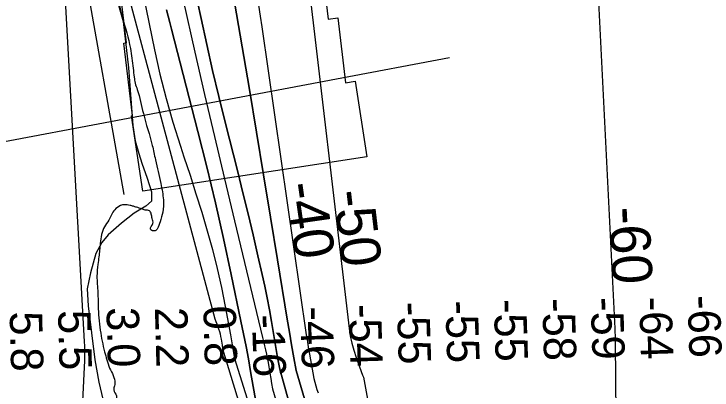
# Model space of a CAD drawing. Extents: x 3694830 to 3732949, y 415201 to 440970.
# Drawn here: x 3716134 to 3717574, y 423394 to 424171 of the extents above; entities that cross this region are included whole.
import ezdxf

# ---------------------------------------------------------------- set-up
doc = ezdxf.new("R2010")
doc.units = 0
for name, color, linetype in [('V-RIVR-EDGE', 7, 'Continuous'), ('V-RIVR-RANG', 7, 'Continuous'), ('V-RRAP-FSHR', 7, 'Continuous'), ('V-RRAP-RVMT', 7, 'Continuous'), ('V-SITE-VEGE', 7, 'Continuous'), ('V-TOPO-DPTH', 7, 'Continuous'), ('V-TOPO-MAJR', 7, 'Continuous'), ('V-TOPO-MAJR-IDEN', 7, 'Continuous'), ('V-TOPO-MINR', 7, 'Continuous'), ('V-TOPO-MINR-IDEN', 7, 'Continuous'), ('V-TOPO-WATR', 7, 'Continuous')]:
    doc.layers.add(name, color=color, linetype=linetype)

msp = doc.modelspace()

# ---------------------------------------------------------------- linework, layer by layer
at = {"layer": 'V-RIVR-EDGE'}
for points in [[(3716285.2, 433216.7), (3716310.4, 433178.2), (3716330.2, 433149.7), (3716351.4, 433122.5), (3716380.7, 433076.8), (3716399.1, 433050.5), (3716447.8, 432976.2), (3716475.3, 432930.5), (3716501.8, 432891.1), (3716527.5, 432851.2), (3716586, 432749.3), (3716608.1, 432711.8), (3716608.1, 432707.7), (3716608.1, 432700.4), (3716613, 432690.9), (3716627.4, 432664.2), (3716633.3, 432651.6), (3716643.2, 432639.3), (3716675.2, 432589.5), (3716706.2, 432538.3), (3716726.9, 432498), (3716741.3, 432463.6), (3716748.5, 432442.8), (3716788.6, 432378.5), (3716817.4, 432339.6), (3716842.2, 432297.4), (3716889.5, 432209.6), (3716920.5, 432144.4), (3716938, 432109.6), (3716956.5, 432075.2), (3716988.9, 432022.6), (3717009.2, 431986.9), (3717026.3, 431960.1), (3717062.3, 431897.6), (3717093.4, 431840.1), (3717112.3, 431799.9), (3717149.1, 431711.1), (3717176.5, 431644.6), (3717201.2, 431580.8), (3717210.7, 431556.4), (3717248.5, 431478.9), (3717267.8, 431435.5), (3717289.4, 431392.9), (3717306.5, 431346.8), (3717328.1, 431301), (3717339.3, 431276.6), (3717352.3, 431244), (3717362.7, 431226.4), (3717376.2, 431205.5), (3717389.3, 431178.4), (3717401.4, 431141.7), (3717407.2, 431113.2), (3717409.9, 431101.9), (3717419.7, 431075.6), (3717452.5, 430968.9), (3717469.1, 430916.8), (3717483.4, 430865.2), (3717505.5, 430810), (3717526.6, 430753.4), (3717540.5, 430715.4), (3717579.1, 430593.2), (3717599.3, 430526.3), (3717616.3, 430474.7), (3717628.9, 430437.1), (3717638.7, 430405), (3717647.7, 430364.3), (3717653.5, 430331.7), (3717658.4, 430314.5), (3717667.9, 430290.1), (3717679.5, 430260.7), (3717690.3, 430242.1), (3717695.7, 430221.3), (3717698.4, 430200), (3717697.9, 430172), (3717701.4, 430153), (3717705.9, 430140.8), (3717716.3, 430119.9), (3717728, 430100.5), (3717735.6, 430076.5), (3717737.8, 430059.3), (3717749, 430029.9), (3717760.8, 430011.8), (3717771.6, 429990), (3717776.5, 429968.3), (3717783.2, 429941.6), (3717791.7, 429917.6), (3717803.4, 429898.6), (3717812.4, 429876.5), (3717819.2, 429857.4), (3717834.9, 429816.7), (3717846.5, 429770.1), (3717854.1, 429734.8), (3717863.5, 429706.3), (3717878.8, 429667.4), (3717891.4, 429622.6), (3717903.5, 429586.4), (3717917.8, 429530.3), (3717931.7, 429476.4), (3717959.5, 429363.8), (3717976.5, 429307.2), (3717987.2, 429262.4), (3718014.1, 429153.9), (3718027.5, 429090.1), (3718040.5, 429028.1), (3718052.5, 428962.5), (3718057.8, 428920), (3718056.9, 428903.3), (3718056.9, 428887.9), (3718057.7, 428868.4), (3718061.3, 428850.8), (3718065.8, 428833.6), (3718082.4, 428779.3), (3718091.3, 428748.1), (3718100.3, 428711), (3718111.4, 428657.1), (3718116.4, 428631.8), (3718128.3, 428526), (3718136.8, 428473.1), (3718141.7, 428440), (3718152.3, 428360.9), (3718163.9, 428291.2), (3718171, 428256.4), (3718178.2, 428236.5), (3718193.9, 428178.6), (3718199.7, 428157.3), (3718197.9, 428150.1), (3718196.5, 428133.3), (3718197.4, 428121.1), (3718204.1, 428098), (3718215.4, 428075.4), (3718228, 428049.6), (3718240.1, 428011.6), (3718242.7, 427978.6), (3718251.1, 427901.2), (3718254.2, 427852.9), (3718257.7, 427822.1), (3718271.5, 427736.2), (3718281.7, 427671.9), (3718287.9, 427606.3), (3718295.9, 427551.6), (3718303.9, 427477.4), (3718310.1, 427447.1), (3718323.1, 427407.8), (3718345.1, 427350.3), (3718351.4, 427321.8), (3718363.5, 427267.5), (3718378.3, 427217.3), (3718398, 427141.2), (3718402.9, 427105.5), (3718405.9, 427056.7), (3718404.9, 426993.4), (3718419.6, 426915.1), (3718427.1, 426857.7), (3718428.8, 426789.8), (3718439.5, 426753.2), (3718453.9, 426709.8), (3718458.3, 426677.2), (3718461.8, 426625.2), (3718465.3, 426583.6), (3718482.7, 426479.5), (3718492.5, 426423.9), (3718501, 426378.2), (3718502.7, 426350.2), (3718512.9, 426256.1), (3718518.2, 426213.1), (3718524, 426182.8), (3718533.4, 426148.9), (3718540.9, 426069.3), (3718548.9, 426010.9), (3718557.8, 425944.4), (3718573.4, 425858.9), (3718584.5, 425787.5), (3718587.6, 425745.4), (3718587.6, 425726), (3718607.5, 425567.2), (3718614.6, 425488.1), (3718638.2, 425368.6), (3718641.3, 425318.4), (3718641.1, 425249.7), (3718640.1, 425214), (3718649.8, 425130.8), (3718658.7, 425069.3), (3718661.8, 425037.2), (3718660.4, 425016.4), (3718675, 424864.4), (3718675.7, 424812.8), (3718692.6, 424694.8), (3718696.1, 424618.8), (3718696.4, 424575.9), (3718706.1, 424484.5), (3718711.9, 424431.6), (3718715.4, 424403.1), (3718735.9, 424289.1), (3718746.6, 424215.4), (3718759.9, 424108.6), (3718772.4, 424027.2), (3718777.7, 423998.3), (3718795.9, 423858), (3718805.7, 423804.2), (3718812.4, 423776.6), (3718829, 423707.4), (3718835.7, 423662.6), (3718835.1, 423612), (3718835, 423576.7), (3718839.3, 423505.3), (3718842.4, 423460), (3718850.4, 423412.5), (3718863.4, 423357.8), (3718870.6, 423326.6), (3718873.6, 423260.5), (3718878.9, 423209), (3718893.6, 423148.4), (3718899, 423126.2), (3718912.4, 423080), (3718927.2, 423022.6), (3718930.8, 422992.7), (3718937.4, 422950.2), (3718945.9, 422900.5), (3718952.6, 422870.6), (3718968.7, 422795.9), (3718969.6, 422769.7), (3718968.1, 422738.5), (3718972.1, 422707.8), (3718981, 422661.2), (3718990.8, 422602.8), (3719006.9, 422506.5), (3719010.8, 422446.3), (3719014.4, 422425.1), (3719022.4, 422393.4), (3719033.2, 422359), (3719050.3, 422307.9), (3719062.8, 422249.1), (3719077.1, 422190.2), (3719087.8, 422149.1)], [(3715510.2, 429495), (3715519.4, 429459.4), (3715532.6, 429419.7), (3715534.2, 429406), (3715534.6, 429397.9), (3715533.8, 429394.7), (3715530.1, 429389.8), (3715520.8, 429385.4), (3715520.4, 429383.8), (3715529.2, 429357.1), (3715587, 429194.8), (3715589.1, 429189.1), (3715589.8, 429179.8), (3715594.7, 429167.3), (3715599.5, 429156.7), (3715608.4, 429150.6), (3715608.4, 429143.8), (3715610.7, 429128.4), (3715615.6, 429112.2), (3715631.6, 429074.6), (3715650.1, 429029.2), (3715664.6, 428990.4), (3715673.8, 428948.3), (3715681.8, 428932.1), (3715694.7, 428908.6), (3715704.7, 428877), (3715710.7, 428847.5), (3715716.7, 428803.4), (3715725.1, 428773.5), (3715730.3, 428739.1), (3715736.6, 428685.3), (3715740.6, 428651.7), (3715742.6, 428635.1), (3715750.2, 428602), (3715756.2, 428579.3), (3715763.8, 428568), (3715770.3, 428560.7), (3715775.9, 428548.5), (3715779.5, 428526.3), (3715782.3, 428514.1), (3715787.1, 428503.6), (3715794.8, 428492.7), (3715802.4, 428486.6), (3715812.9, 428475.2), (3715818.2, 428463.1), (3715822.6, 428444.1), (3715822.9, 428427.1), (3715822.1, 428409.3), (3715816.4, 428393.5), (3715813.9, 428385.5), (3715810.2, 428364.9), (3715808.6, 428348.3), (3715810.1, 428326), (3715814.1, 428296.1), (3715814.9, 428282.4), (3715814.8, 428265.4), (3715814, 428246.4), (3715819.2, 428212), (3715825.5, 428176.8), (3715828.3, 428148.5), (3715834.3, 428123.4), (3715842.4, 428110), (3715849.6, 428100.3), (3715854, 428086.1), (3715854.8, 428064.7), (3715853.5, 428030.7), (3715846.1, 427990.7), (3715841.2, 427968.1), (3715841.2, 427956.4), (3715841.1, 427943.8), (3715851.6, 427910.2), (3715867.2, 427862.5), (3715873.6, 427835.8), (3715876, 427815.6), (3715876, 427799.4), (3715870.3, 427782), (3715868.6, 427769.5), (3715868.6, 427757.3), (3715873.7, 427723), (3715882.1, 427684.5), (3715885.3, 427654.6), (3715884, 427624.3), (3715879.5, 427578.6), (3715878.1, 427541.4), (3715878.8, 427496.5), (3715875.5, 427454.1), (3715874.6, 427412), (3715872.9, 427377.6), (3715869.6, 427336.4), (3715866.3, 427310.1), (3715865.8, 427291.5), (3715867.4, 427264), (3715873.3, 427234.5), (3715883.8, 427200.5), (3715895, 427166.5), (3715899.8, 427143.8), (3715900.2, 427120.8), (3715892.8, 427089.3), (3715886.7, 427071.1), (3715883.4, 427055.7), (3715883.4, 427037.9), (3715885.4, 427020.9), (3715899.8, 426986.1), (3715910.3, 426959), (3715917.1, 426933.5), (3715925.1, 426900.3), (3715927.9, 426873.7), (3715928.2, 426853), (3715928.1, 426806.5), (3715927.6, 426760.8), (3715929.5, 426734.1), (3715927, 426703.4), (3715921.7, 426671.5), (3715916.8, 426641.6), (3715917.1, 426618.5), (3715918.7, 426593.4), (3715921.4, 426562.3), (3715922.2, 426531.6), (3715931.7, 426461.6), (3715934, 426424.8), (3715934.8, 426396.5), (3715937.5, 426364.9), (3715941.4, 426303.9), (3715943.7, 426258.2), (3715946.1, 426223), (3715949.6, 426185.4), (3715954.7, 426102.9), (3715958.6, 426073.7), (3715967.4, 426016.7), (3715974.5, 425960.5), (3715974.9, 425934.2), (3715982.4, 425875.1), (3715988, 425832.7), (3715990.7, 425805.2), (3715996.3, 425788.6), (3716003.6, 425763.9), (3716005.5, 425745.3), (3716009.8, 425685.8), (3716015, 425646.2), (3716020.1, 425601.7), (3716024.1, 425552.7), (3716029.2, 425516.3), (3716032.8, 425488.4), (3716038.8, 425450.8), (3716039.9, 425423.3), (3716046.7, 425372.7), (3716051.1, 425349.3), (3716057.4, 425317.7), (3716059.8, 425289), (3716060.2, 425266.8), (3716063.7, 425234), (3716070.9, 425189.5), (3716078.1, 425159.6), (3716092.1, 425118.3), (3716107.4, 425074.2), (3716115, 425041.8), (3716120.6, 425016.3), (3716122.2, 425003), (3716126.1, 424943.9), (3716130, 424894.6), (3716131.2, 424880), (3716134.8, 424856.1), (3716142.7, 424795.1), (3716147.5, 424765.1), (3716151.9, 424739.6), (3716155.9, 424721.4), (3716163.1, 424703.2), (3716186, 424653.8), (3716195.7, 424627.1), (3716208.9, 424591.5), (3716230.2, 424544.1), (3716256.4, 424502), (3716274.1, 424469.2), (3716284.6, 424452.2), (3716301.1, 424424.7), (3716313.6, 424398.4), (3716323.6, 424368), (3716332.4, 424330.8), (3716336.4, 424302.9), (3716343.1, 424241.8), (3716348.3, 424203), (3716353.5, 424178.7), (3716357.5, 424163.3), (3716373.9, 424099.4), (3716379.4, 424058.5), (3716381.8, 424039.9), (3716383.8, 424027.8), (3716388.2, 424014.4), (3716400.6, 423964.7), (3716419.1, 423899.1), (3716425.5, 423869.6), (3716436.7, 423820.2), (3716441.9, 423786.6), (3716440.6, 423761.2), (3716435.3, 423741.4), (3716429.2, 423726.4), (3716425.1, 423722.8), (3716421.5, 423722.4), (3716417.8, 423723.6), (3716415.4, 423726), (3716420.3, 423737.8), (3716418.7, 423748.3), (3716417.1, 423757.2), (3716413.1, 423763.7), (3716404.2, 423765.7), (3716397.3, 423768.1), (3716386.4, 423771.4), (3716380, 423773.4), (3716373.1, 423775.1), (3716361.8, 423776.7), (3716353.7, 423774.7), (3716341.5, 423766.3), (3716329.3, 423744.9), (3716320.4, 423731.1), (3716311.8, 423697.2), (3716308.9, 423668.9), (3716306.4, 423653.3)], [(3716306.4, 423653.3), (3716304.8, 423629.3), (3716306.7, 423595.3), (3716307.5, 423567.4), (3716308.6, 423543.1), (3716311.8, 423517.2), (3716320.6, 423473.1), (3716330.8, 423439.3)], [(3716330.8, 423439.3), (3716341.8, 423408), (3716341, 423402.3), (3716339.4, 423394.2), (3716345, 423382.1), (3716345, 423377.7), (3716344.2, 423371.2), (3716344.2, 423362.3), (3716353.8, 423346.9), (3716354.2, 423340), (3716354.2, 423329.5), (3716353.8, 423325.1), (3716358.2, 423319.4), (3716369.1, 423317.7), (3716377.2, 423314.1), (3716381.6, 423305.2), (3716389.2, 423278.5), (3716394, 423251.8), (3716404.1, 423221), (3716418.5, 423185.8), (3716443.1, 423127.5), (3716459.1, 423083), (3716478, 423026.3), (3716495.3, 422990.3), (3716511.8, 422957.1), (3716527.1, 422922.7), (3716536.3, 422888.3), (3716539.5, 422868.5), (3716545.1, 422839.3), (3716549.4, 422814.7), (3716553, 422796.1), (3716571.9, 422741.4), (3716593.6, 422675.1), (3716607.6, 422637.8), (3716616.9, 422610.7), (3716635.3, 422558.1), (3716647.4, 422520.4), (3716673.9, 422447)]]:
    msp.add_spline(points, degree=3, dxfattribs=at)
at = {"layer": 'V-RIVR-RANG'}
msp.add_line((3716069.8, 423898.9), (3717032.8, 424080.6), dxfattribs=at)
at = {"layer": 'V-RRAP-FSHR'}
msp.add_lwpolyline([(3714934.3, 430879.4), (3715310.8, 430066.4), (3715565.7, 429152.3), (3715743.6, 427937.5), (3715907.8, 426518.2), (3715968.2, 425803.5), (3716063.3, 425015.1), (3716110.2, 424867.2), (3716274.4, 424283), (3716360.4, 423797.4)], dxfattribs=at)
at = {"layer": 'V-RRAP-RVMT'}
msp.add_lwpolyline([(3716743, 424300.8), (3716765.2, 424303.5), (3716782.3, 424160.1), (3716802.3, 424162.4), (3716818.1, 424028.5), (3716838.1, 424031.6), (3716862.1, 423875.5), (3716399.9, 423804.4), (3716375.9, 423960.4), (3716378, 423960.8), (3716360.3, 424110.1), (3716365.7, 424110.7), (3716348.8, 424254.1)], dxfattribs=at)
at = {"layer": 'V-SITE-VEGE'}
msp.add_lwpolyline([(3716349.2, 424189), (3716359, 424154.8), (3716369.7, 424059.6), (3716378.7, 423940.4), (3716383.8, 423908.6), (3716391.3, 423882.3), (3716397.3, 423862.1), (3716408.7, 423831.8), (3716417.7, 423803.1), (3716417.5, 423783.8), (3716405.8, 423773.8), (3716381.7, 423759.4), (3716355.2, 423738.7), (3716327.9, 423714.2), (3716314.6, 423698.9), (3716302.8, 423675.8), (3716291.6, 423635.6), (3716284.4, 423603.2), (3716286.4, 423567.6), (3716300.8, 423456.1), (3716308.9, 423410.4), (3716320.1, 423363.1)], dxfattribs=at)
at = {"layer": 'V-TOPO-DPTH'}
for points in [[(3716498.3, 425071.1), (3716500.9, 425043), (3716503.6, 425015), (3716569.4, 424335.2), (3716572.7, 424305.1), (3716576.3, 424275.1), (3716580.7, 424245.2), (3716585.4, 424215.3), (3716619.4, 424014.4), (3716634.2, 423926.5), (3716648.9, 423838.6), (3716663.4, 423750.7), (3716677.8, 423662.8), (3716697.8, 423539.9), (3716702.2, 423513.4), (3716706.6, 423487), (3716711.3, 423460.5), (3716716, 423434.1), (3716936.1, 422685.3)], [(3716936.1, 422685.3), (3716716, 423434.1), (3716711.3, 423460.5), (3716706.6, 423487), (3716702.2, 423513.4), (3716697.8, 423539.9), (3716677.8, 423662.8), (3716663.4, 423750.7), (3716648.9, 423838.6), (3716634.2, 423926.5), (3716619.4, 424014.4), (3716585.4, 424215.3), (3716580.7, 424245.2), (3716576.3, 424275.1), (3716572.7, 424305.1), (3716569.4, 424335.2), (3716503.6, 425015), (3716500.9, 425043), (3716498.3, 425071.1)], [(3716362.4, 424236.7), (3716548.3, 423540.7), (3716550.4, 423535.6), (3716552.3, 423530.5), (3716554.2, 423525.4), (3716555.9, 423520.2), (3716557.5, 423515), (3716558.9, 423509.7), (3716560.1, 423504.4), (3716561.1, 423499), (3716563.2, 423486.4), (3716563.5, 423484.6), (3716563.8, 423482.8), (3716564, 423481), (3716564.3, 423479.1), (3716812.1, 422663.8)], [(3716505.1, 424230.8), (3716519.9, 424161.3), (3716531.5, 424107.5), (3716543.6, 424053.8), (3716556.4, 424000.3), (3716569.5, 423946.9), (3716595.3, 423844.3), (3716606.1, 423801.1), (3716616.7, 423757.8), (3716627, 423714.5), (3716637.1, 423671.1), (3716645.9, 423632.8), (3716651.2, 423608.5), (3716656.3, 423584.1), (3716660.9, 423559.6), (3716665.1, 423535.1), (3716669.2, 423510.5), (3716673.4, 423486), (3716677.7, 423461.4), (3716682.1, 423436.9), (3716884.9, 422705.6)], [(3716884.9, 422705.6), (3716682.1, 423436.9), (3716677.7, 423461.4), (3716673.4, 423486), (3716669.2, 423510.5), (3716665.1, 423535.1), (3716660.9, 423559.6), (3716656.3, 423584.1), (3716651.2, 423608.5), (3716645.9, 423632.8), (3716637.1, 423671.1), (3716627, 423714.5), (3716616.7, 423757.8), (3716606.1, 423801.1), (3716595.3, 423844.3), (3716569.5, 423946.9), (3716556.4, 424000.3), (3716543.6, 424053.8), (3716531.5, 424107.5), (3716519.9, 424161.3), (3716505.1, 424230.8)], [(3716634.3, 423362.8), (3716622, 423432.2), (3716617.4, 423458.2), (3716612.5, 423484.1), (3716607.4, 423510), (3716602.1, 423535.9), (3716581.9, 423632.7), (3716565.9, 423706.8), (3716549.3, 423780.8), (3716531.5, 423854.6), (3716513.1, 423928.1), (3716458.7, 424139.3), (3716455.2, 424152.7), (3716451.7, 424166.1), (3716448.2, 424179.4)], [(3716634.3, 423362.8), (3716622, 423432.2), (3716617.4, 423458.2), (3716612.5, 423484.1), (3716607.4, 423510), (3716602.1, 423535.9), (3716581.9, 423632.7), (3716565.9, 423706.8), (3716549.3, 423780.8), (3716531.5, 423854.6), (3716513.1, 423928.1), (3716458.7, 424139.3), (3716455.2, 424152.7), (3716451.7, 424166.1), (3716448.2, 424179.4)], [(3716638.4, 424188.7), (3716641.7, 424166.2), (3716644.9, 424143.7), (3716737, 423507.9), (3716738.5, 423497.9), (3716740.1, 423487.9), (3716741.7, 423478), (3716743.5, 423468), (3716752.8, 423417.4), (3716754.4, 423410), (3716756.3, 423402.5), (3716758.8, 423395.3), (3716761.5, 423388.1)], [(3716638.4, 424188.7), (3716641.7, 424166.2), (3716644.9, 424143.7), (3716737, 423507.9), (3716738.5, 423497.9), (3716740.1, 423487.9), (3716741.7, 423478), (3716743.5, 423468), (3716752.8, 423417.4), (3716754.4, 423410), (3716756.3, 423402.5), (3716758.8, 423395.3), (3716761.5, 423388.1)]]:
    msp.add_lwpolyline(points, dxfattribs=at)
at = {"layer": 'V-TOPO-MAJR'}
msp.add_lwpolyline([(3716560.7, 426173.2), (3716581.9, 425959.3), (3716593.2, 425843.5), (3716604, 425727.7), (3716614.4, 425611.8), (3716624.4, 425495.9), (3716647.3, 425222.3), (3716648.5, 425208), (3716649.8, 425193.7), (3716651.1, 425179.4), (3716652.4, 425165.2), (3716735.3, 424287.4), (3716825.4, 423521.2), (3716827.8, 423506), (3716830.8, 423490.9), (3716834.9, 423476), (3716839.7, 423461.4), (3716853, 423424.6), (3716854.7, 423420.6), (3716989.5, 422683.9)], dxfattribs=at)
at = {"layer": 'V-TOPO-MINR'}
for points in [[(3715985.9, 426095.6), (3716079.5, 425157.2), (3716236.8, 424248.7), (3716278.8, 423494.1), (3716279.2, 423484.3), (3716279.3, 423474.5), (3716279.2, 423464.7), (3716278.9, 423455), (3716272.7, 423329)], [(3717045.2, 426008.2), (3717056.9, 425976.8), (3717067.7, 425945), (3717077.6, 425912.8), (3717087.2, 425880.6), (3717096.4, 425848.2), (3717105.3, 425815.8), (3717125.4, 425741), (3717144.6, 425671.2), (3717164.4, 425601.6), (3717184.9, 425532.2), (3717206, 425463), (3717277.1, 425233.9), (3717333.5, 424333.8), (3717373.7, 423520.8), (3717374, 423513.6), (3717374.2, 423506.3), (3717374.4, 423499), (3717374.5, 423491.7), (3717375.9, 423342.2)], [(3716498.3, 425071.1), (3716500.9, 425043), (3716503.6, 425015), (3716569.4, 424335.2), (3716572.7, 424305.1), (3716576.3, 424275.1), (3716580.7, 424245.2), (3716585.4, 424215.3), (3716619.4, 424014.4), (3716634.2, 423926.5), (3716648.9, 423838.6), (3716663.4, 423750.7), (3716677.8, 423662.8), (3716697.8, 423539.9), (3716702.2, 423513.4), (3716706.6, 423487), (3716711.3, 423460.5), (3716716, 423434.1), (3716936.1, 422685.3)], [(3716505.1, 424230.8), (3716519.9, 424161.3), (3716531.5, 424107.5), (3716543.6, 424053.8), (3716556.4, 424000.3), (3716569.5, 423946.9), (3716595.3, 423844.3), (3716606.1, 423801.1), (3716616.7, 423757.8), (3716627, 423714.5), (3716637.1, 423671.1), (3716645.9, 423632.8), (3716651.2, 423608.5), (3716656.3, 423584.1), (3716660.9, 423559.6), (3716665.1, 423535.1), (3716669.2, 423510.5), (3716673.4, 423486), (3716677.7, 423461.4), (3716682.1, 423436.9), (3716884.9, 422705.6)], [(3716400.6, 424208.2), (3716423.6, 424096.8), (3716434.9, 424046.4), (3716447.4, 423996.3), (3716461.7, 423946.8), (3716477.2, 423897.5), (3716484.5, 423875.6), (3716497, 423837.5), (3716509.2, 423799.3), (3716521, 423760.9), (3716532.5, 423722.5), (3716543.2, 423683.9), (3716553.1, 423645), (3716561.8, 423605.9), (3716569.7, 423566.6), (3716580.6, 423508), (3716582.8, 423495.7), (3716584.9, 423483.4), (3716586.8, 423471), (3716588.7, 423458.7), (3716816.3, 422732.7)], [(3716482.7, 424199.7), (3716507.2, 424091.9), (3716527.1, 424004.6), (3716547.4, 423917.3), (3716567.9, 423830.2), (3716588.7, 423743), (3716646.7, 423502.4), (3716648.7, 423493.9), (3716650.7, 423485.3), (3716652.7, 423476.7), (3716654.6, 423468.1), (3716656.4, 423459.5), (3716658.1, 423450.8), (3716659.6, 423442.1), (3716661.1, 423433.4), (3716661.8, 423429), (3716663.6, 423418), (3716665.4, 423407.1), (3716667.4, 423396.2), (3716818.6, 422877.5)], [(3716448.2, 424179.4), (3716451.7, 424166.1), (3716455.2, 424152.7), (3716458.7, 424139.3), (3716513.1, 423928.1), (3716531.5, 423854.6), (3716549.3, 423780.8), (3716565.9, 423706.8), (3716581.9, 423632.7), (3716602.1, 423535.9), (3716607.4, 423510), (3716612.5, 423484.1), (3716617.4, 423458.2), (3716622, 423432.2), (3716634.3, 423362.8)], [(3716638.4, 424188.7), (3716641.7, 424166.2), (3716644.9, 424143.7), (3716737, 423507.9), (3716738.5, 423497.9), (3716740.1, 423487.9), (3716741.7, 423478), (3716743.5, 423468), (3716752.8, 423417.4), (3716754.4, 423410), (3716756.3, 423402.5), (3716758.8, 423395.3), (3716761.5, 423388.1)]]:
    msp.add_lwpolyline(points, dxfattribs=at)
at = {"layer": 'V-TOPO-WATR'}
msp.add_lwpolyline([(3716362.4, 424236.7), (3716548.3, 423540.7), (3716550.4, 423535.6), (3716552.3, 423530.5), (3716554.2, 423525.4), (3716555.9, 423520.2), (3716557.5, 423515), (3716558.9, 423509.7), (3716560.1, 423504.4), (3716561.1, 423499), (3716563.2, 423486.4), (3716563.5, 423484.6), (3716563.8, 423482.8), (3716564, 423481), (3716564.3, 423479.1), (3716812.1, 422663.8)], dxfattribs=at)

# ---------------------------------------------------------------- texts
at = {"layer": 'V-RIVR-RANG'}
for s, rotation, p in [('-55', 271.8031, (3717023.9, 423578.1)), ('-55', 271.8031, (3717123.8, 423581)), ('-58', 271.8031, (3717223.8, 423582.8)), ('-59', 271.8031, (3717323.8, 423585)), ('-64', 271.8031, (3717423.8, 423585.7)), ('-66', 271.8031, (3717523.8, 423588.9)), ('3.0', 271.5183, (3716324.4, 423564.3)), ('2.2', 271.5183, (3716424.4, 423564.3)), ('0.8', 271.5183, (3716524.4, 423567.2)), ('-46', 271.8031, (3716724.1, 423565.7)), ('-54', 271.8031, (3716824, 423570.5)), ('-55', 271.8031, (3716923.9, 423575.2)), ('5.8', 271.5183, (3716124.6, 423555.6)), ('5.5', 271.5183, (3716224.5, 423558.5)), ('-16', 271.8031, (3716624.6, 423549.1))]:
    msp.add_text(s, height=67, rotation=rotation, dxfattribs=at).set_placement(p)
at = {"layer": 'V-TOPO-MAJR-IDEN'}
msp.add_text('-50', height=83, rotation=276.7097, dxfattribs=at).set_placement((3716792.2, 423804))
at = {"layer": 'V-TOPO-MINR-IDEN'}
for s, rotation, p in [('-40', 278.2378, (3716691.9, 423819.1)), ('-60', 272.8276, (3717361.3, 423770.9))]:
    msp.add_text(s, height=83, rotation=rotation, dxfattribs=at).set_placement(p)

doc.saveas('drawing.dxf')
